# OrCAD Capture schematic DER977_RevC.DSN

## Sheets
1 PAGE3: size A
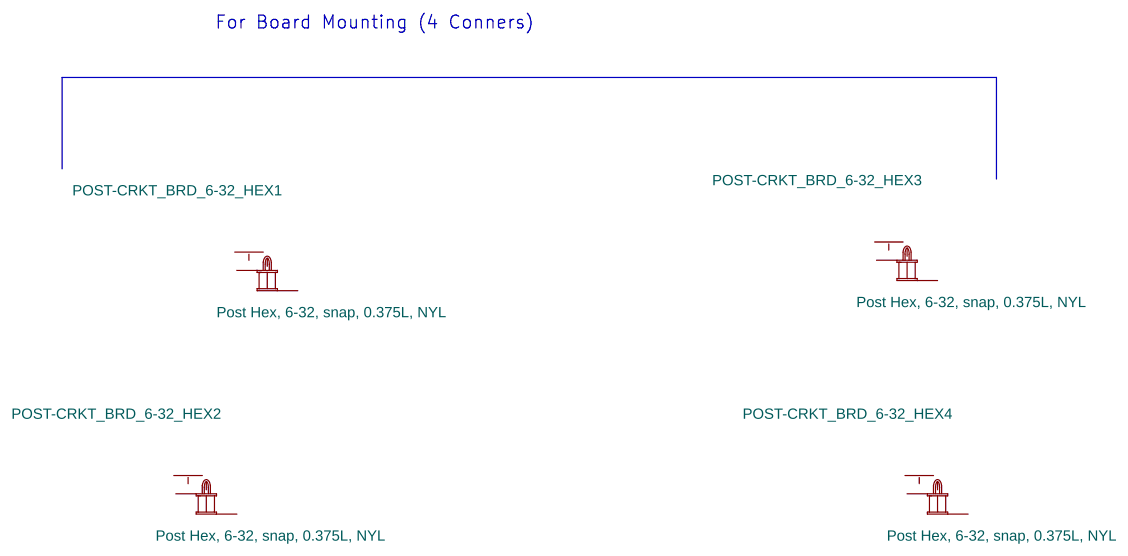
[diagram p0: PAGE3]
2 PAGE2: size C; title: HiperPFS-220W Design
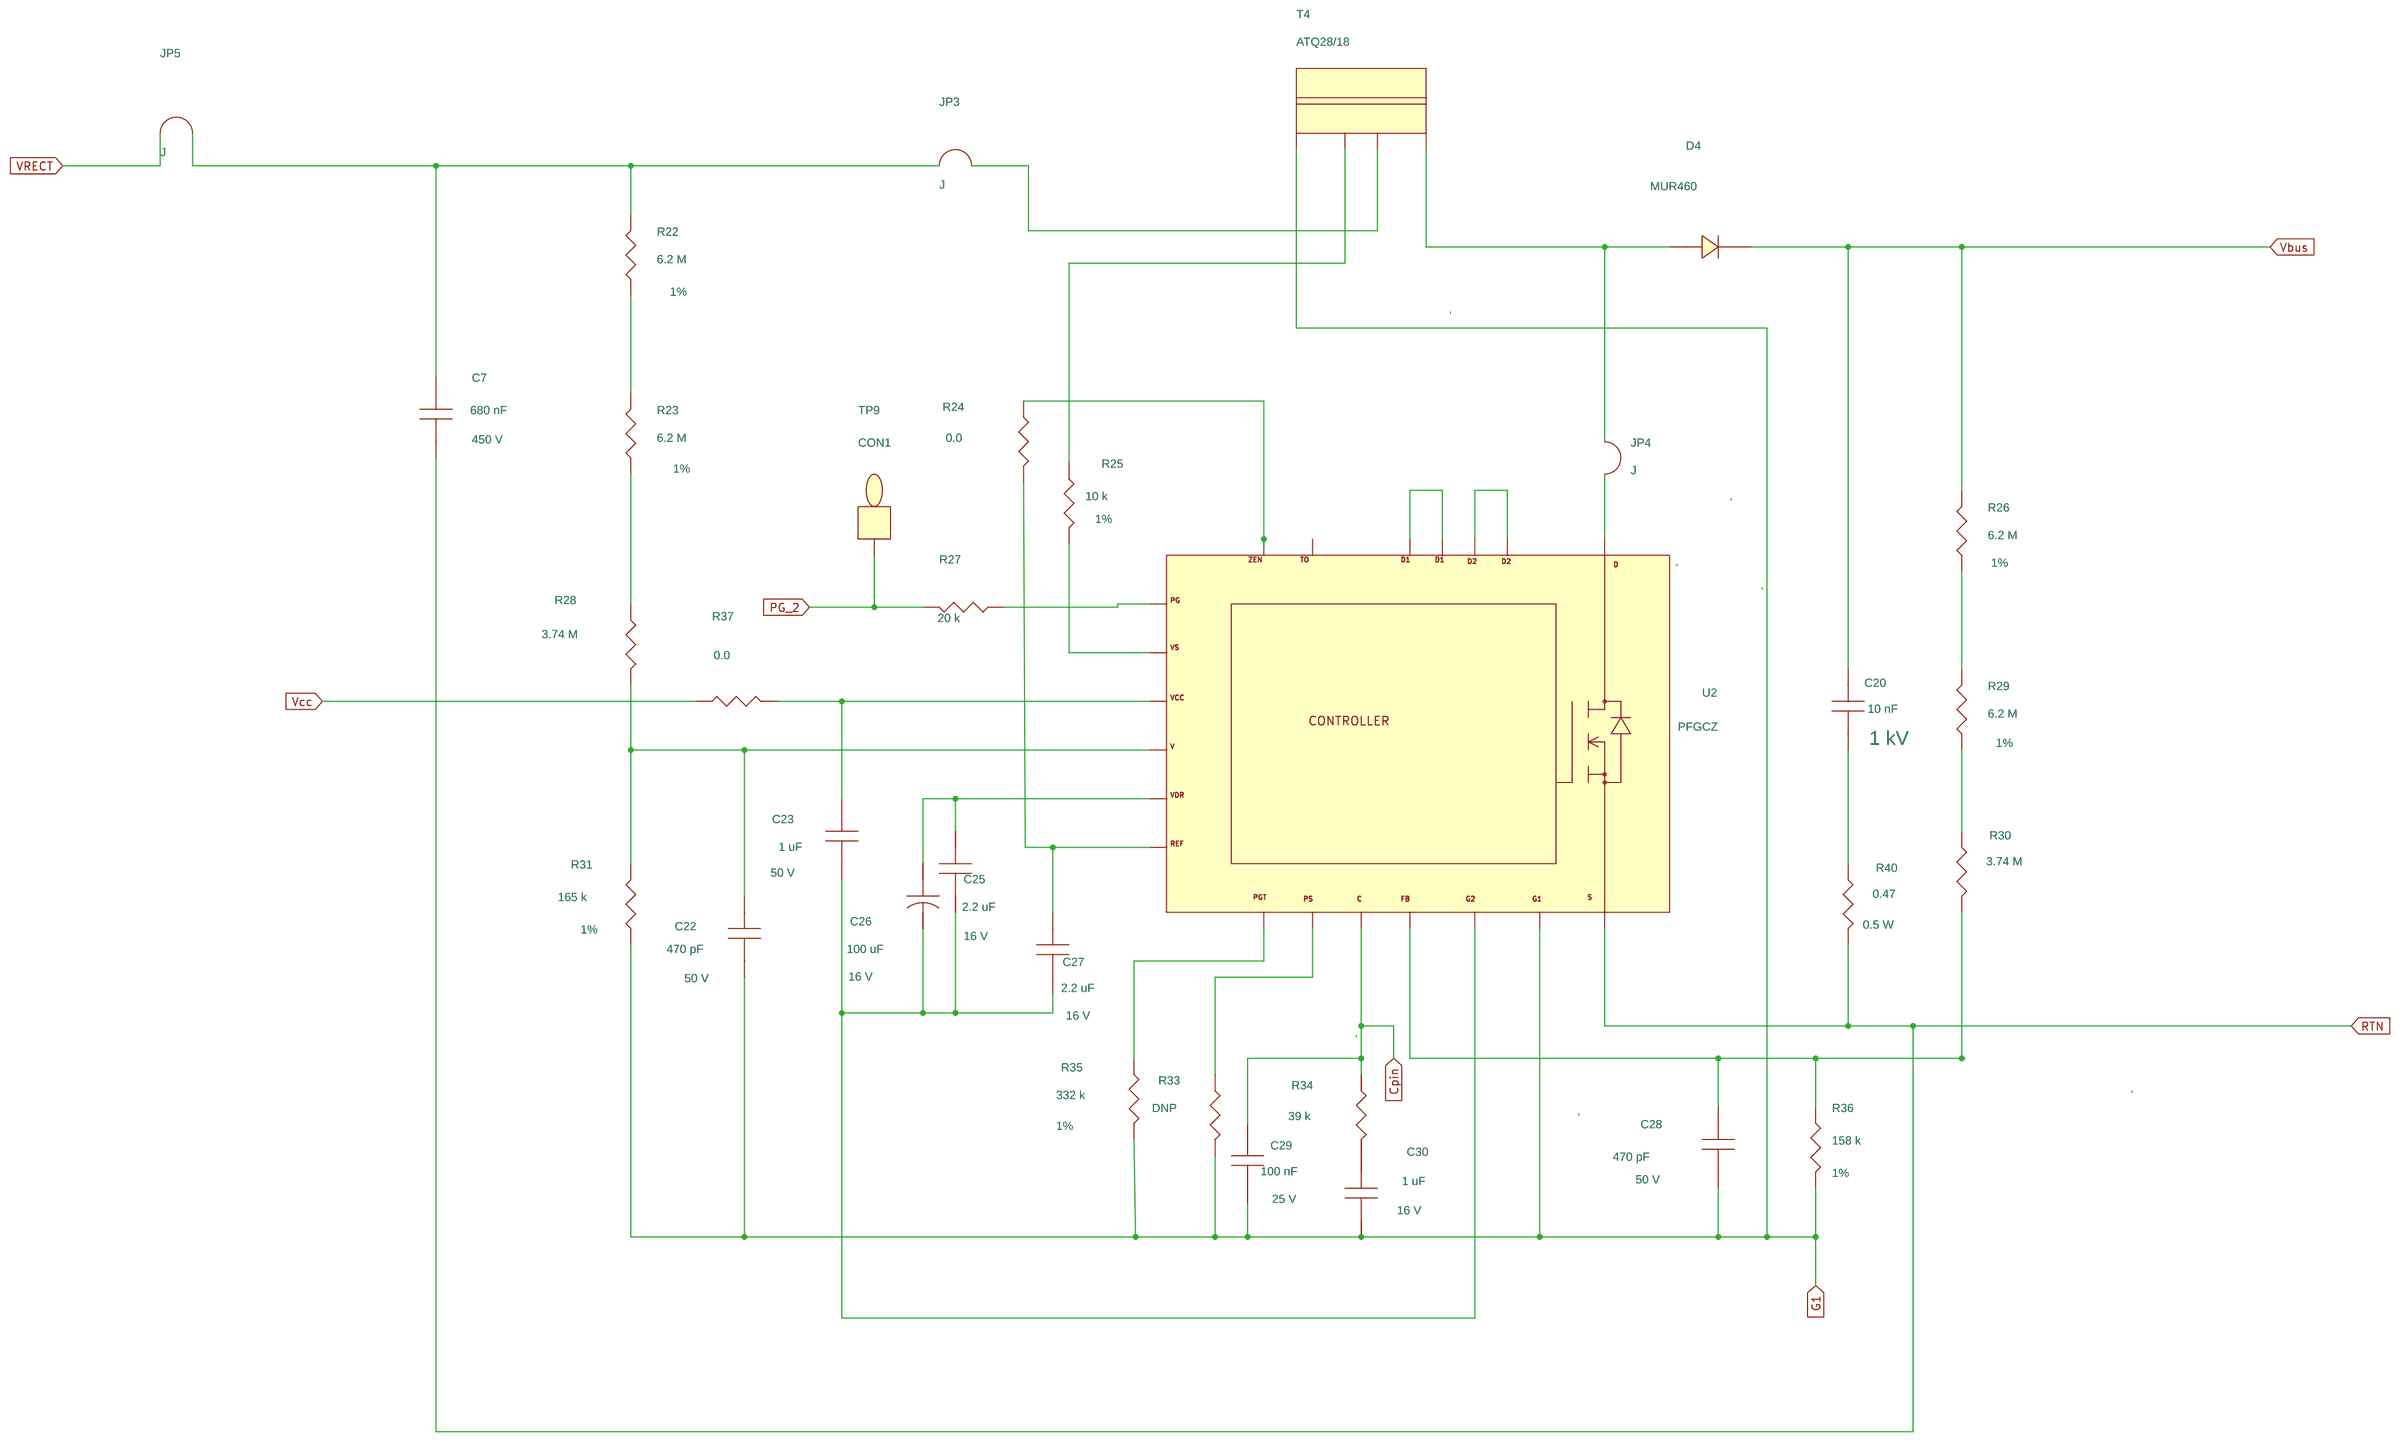
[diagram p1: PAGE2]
3 PAGE1: size C; title: HIPERPFS5 -440W Parallel Board
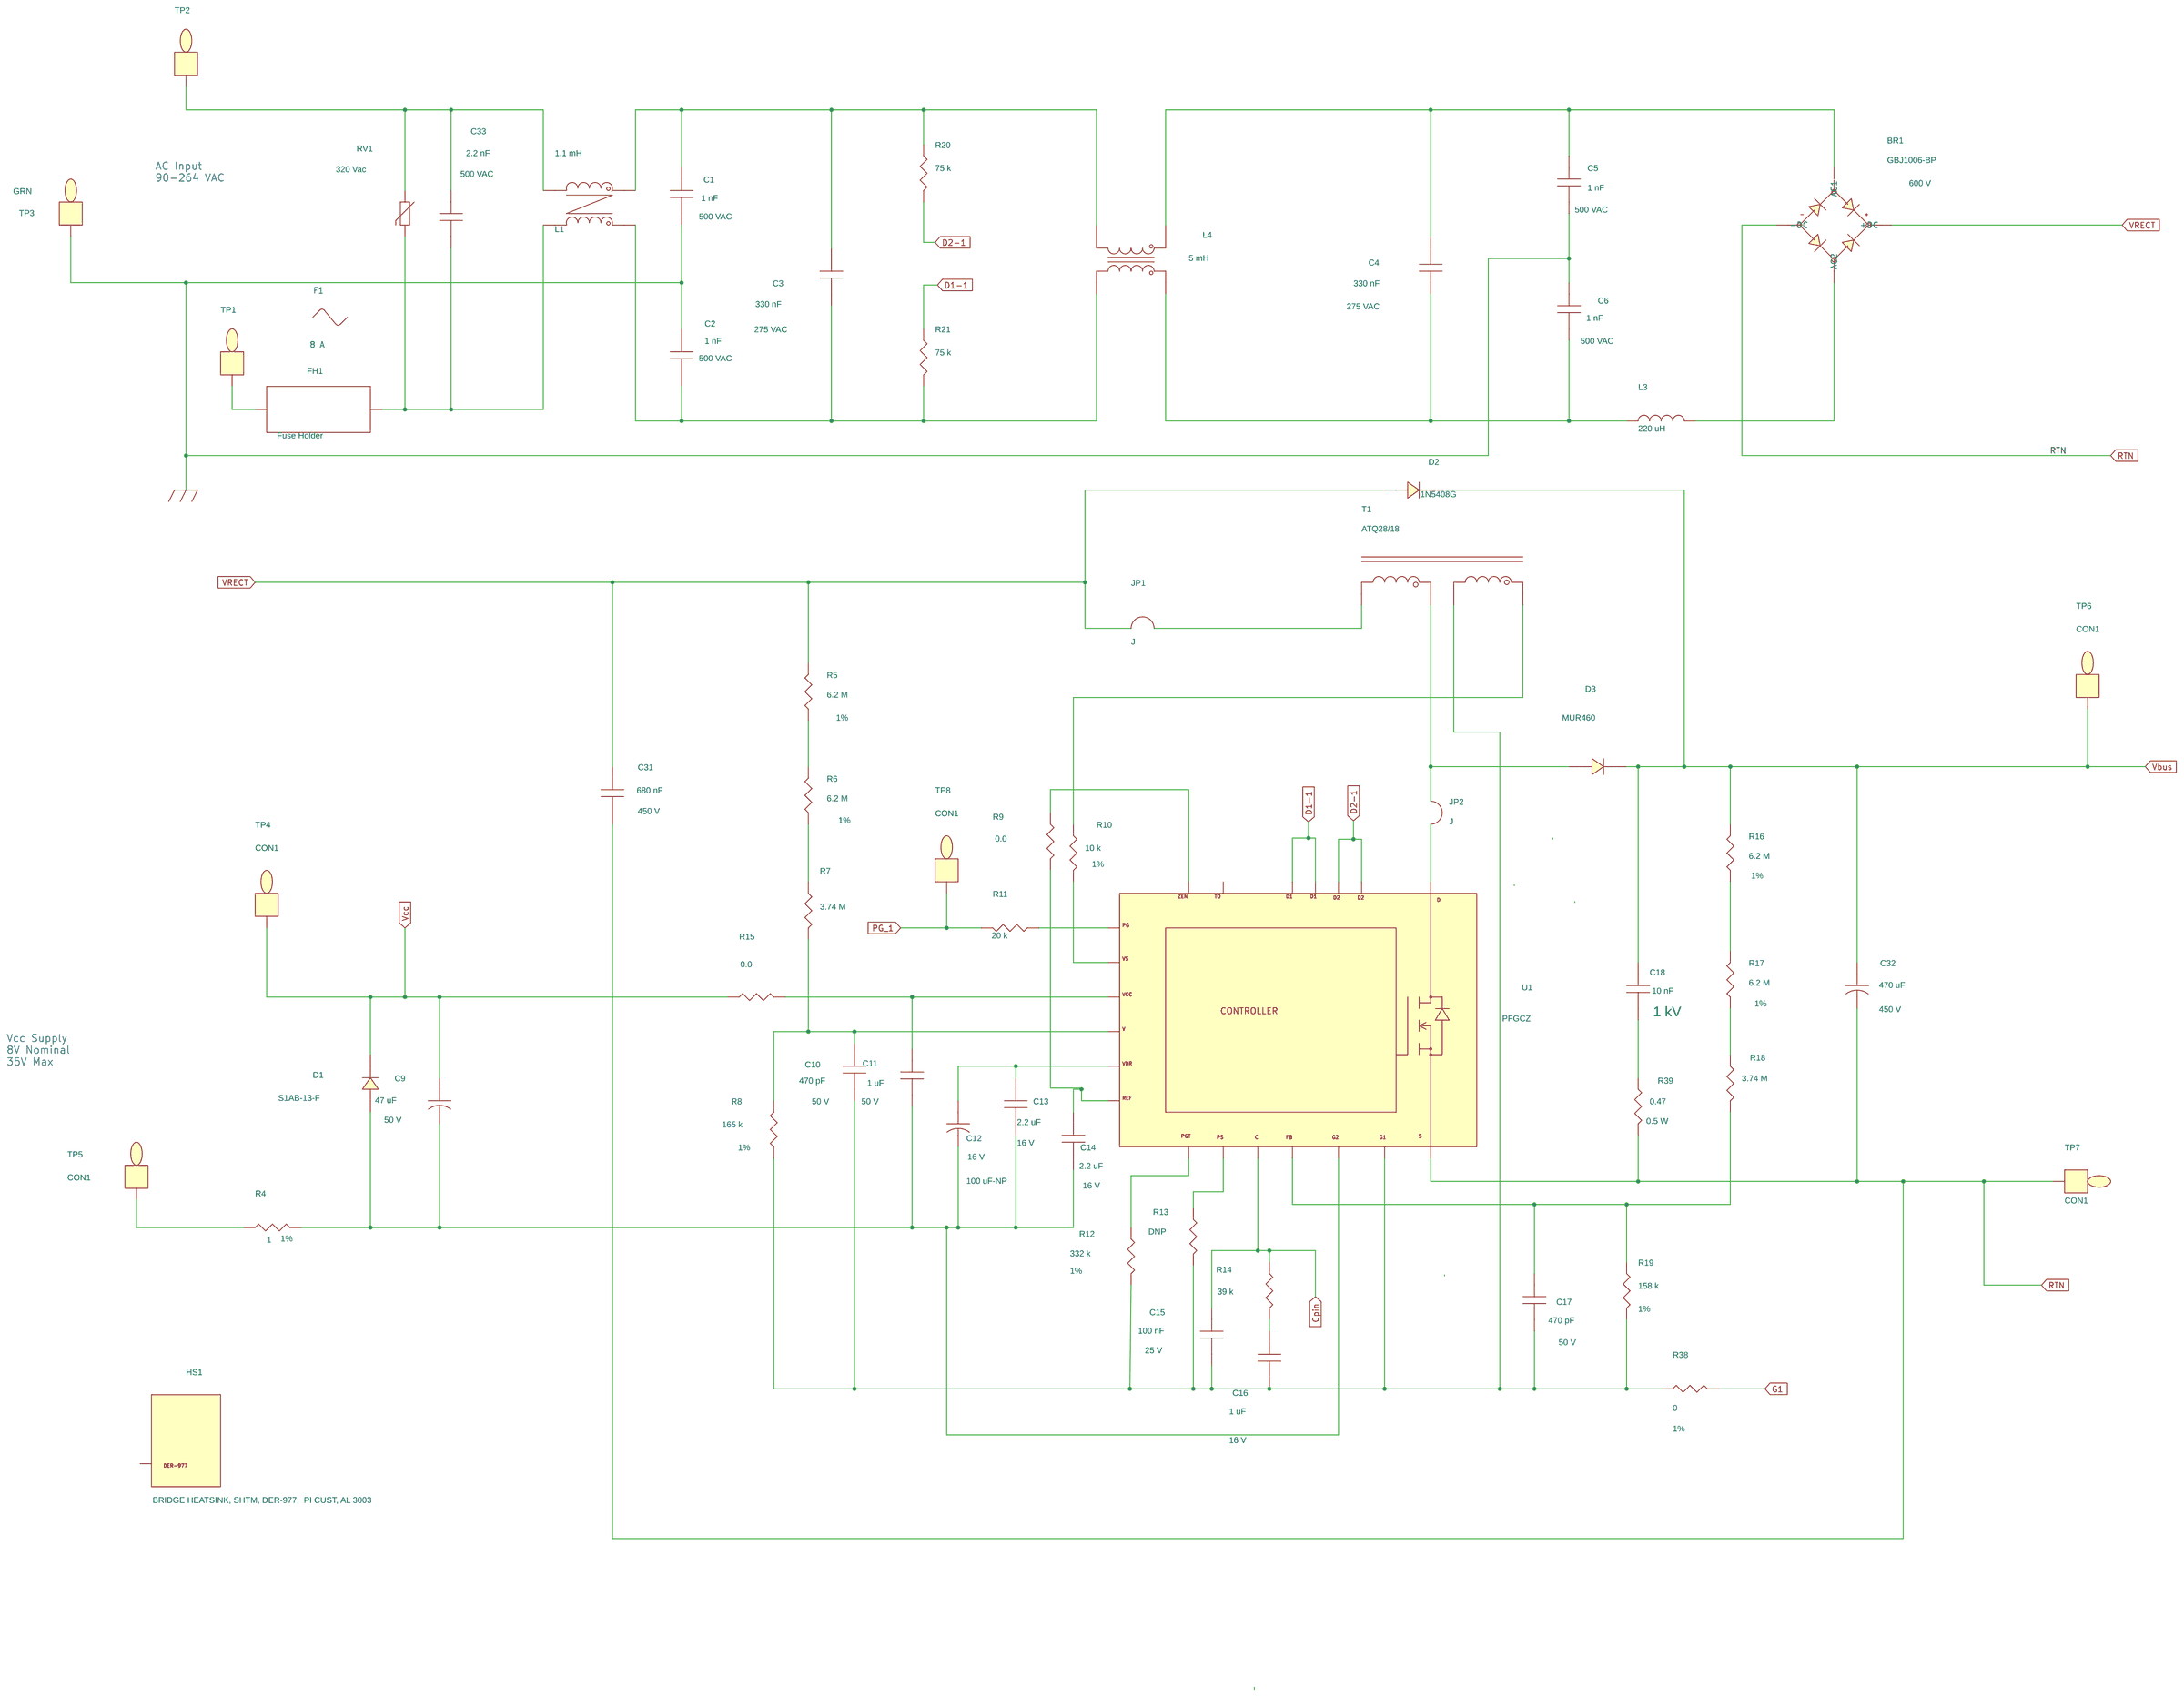
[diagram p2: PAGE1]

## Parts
sheet PAGE1
BR1  GBJ1006-BP  [pi_dax_bridg_gbj]
C1  1 nF  [pi_np475x200ls395d040]
C2  1 nF  [pi_np475x200ls395d040]
C3  330 nF  [pinp_xcaprad15x8p5x14Hd040]
C4  330 nF  [pinp_xcaprad15x8p5x14Hd040]
C5  1 nF  [pi_np475x200ls395d040]
C6  1 nF  [pi_np475x200ls395d040]
C9  47 uF  [pipolcapcyld250ls100030]
C10  470 pF  [pismc0603]
C11  1 uF  [pismc0603]
C12  100 uF-NP  [pipolcapcyld250ls100030]
C13  2.2 uF  [pismc0402]
C14  2.2 uF  [pismc0402]
C15  100 nF  [pismc0603]
C16  1 uF  [pismc0603]
C17  470 pF  [pismc0603]
C18  10 nF  [pi_np_cap250x200ls170d030]
C31  680 nF  [pinpcaprad17p5x6p7ls15]
C32  470 uF  [pipolcapclyd35mmls10]
C33  2.2 nF  [pinpycaprad540x290ls400040]
D1  S1AB-13-F  [pismsmb]
D2  1N5408G  [pidv300x200x060do15d0201ad]
D3  MUR460  [pidv300x200x060do15d0201ad]
F1  8 A
FH1  Fuse Holder  [pi_fuseholder_5x20mm]
HS1  BRIDGE HEATSINK, SHTM, DER-977,  PI CUST, AL 3003  [PI_HS_1P_DER977]
JP1  J  [pi_jumper200]
JP2  J  [pi_jumper200]
L1  1.1 mH  [piind4p22x10ls10mm050]
L3  220 uH  [pi2p30x15x15lsd60]
L4  5 mH  [piind4p1450x800ls900x600050]
R4  1  [pismr1206]
R5  6.2 M  [pismr1206]
R6  6.2 M  [pismr1206]
R7  3.74 M  [pismr1206]
R8  165 k  [pismr0805]
R9  0.0  [pismr0603]
R10  10 k  [pismr0805]
R11  20 k  [pismr0603]
R12  332 k  [pismr0603]
R13  DNP  [pismr0805]
R14  39 k  [pismr0603]
R15  0.0  [pismr0603]
R16  6.2 M  [pismr1206]
R17  6.2 M  [pismr1206]
R18  3.74 M  [pismr1206]
R19  158 k  [pismr0805]
R20  75 k  [pismr1206]
R21  75 k  [pismr1206]
R38  0  [pismr0603]
R39  0.47  [pismr2010]
RV1  320 Vac  [pidisc500x225ls335x140040]
T1  ATQ28/18  [pi_bobbin_ATQ28_V_4P]
TP1  RED  [pitpkeystone125x125]
TP2  CON1  [pitpkeystone125x125]
TP3  GRN  [pitpkeystone125x125]
TP4  CON1  [pitpkeystone125x125]
TP5  CON1  [pitpkeystone125x125]
TP6  CON1  [pitpkeystone125x125]
TP7  CON1  [pitpkeystone125x125]
TP8  CON1  [pitpkeystone125x125]
U1  PFGCZ  [inSOP-T28F]
sheet PAGE2
C7  680 nF  [pinpcaprad17p5x6p7ls15]
C20  10 nF  [pi_np_cap250x200ls170d030]
C22  470 pF  [pismc0603]
C23  1 uF  [pismc0603]
C25  2.2 uF  [pismc0402]
C26  100 uF  [pipolcapcyld250ls100030]
C27  2.2 uF  [pismc0402]
C28  470 pF  [pismc0603]
C29  100 nF  [pismc0603]
C30  1 uF  [pismc0603]
D4  MUR460  [pidv300x200x060do15d0201ad]
JP3  J  [pi_jumper200]
JP4  J  [pi_jumper200]
JP5  J  [pi_jumper1800-18awg-sld]
R22  6.2 M  [pismr1206]
R23  6.2 M  [pismr1206]
R24  0.0  [pismr0603]
R25  10 k  [pismr0805]
R26  6.2 M  [pismr1206]
R27  20 k  [pismr0603]
R28  3.74 M  [pismr1206]
R29  6.2 M  [pismr1206]
R30  3.74 M  [pismr1206]
R31  165 k  [pismr0805]
R33  DNP  [pismr0805]
R34  39 k  [pismr0603]
R35  332 k  [pismr0603]
R36  158 k  [pismr0805]
R37  0.0  [pismr0603]
R40  0.47  [pismr2010]
T4  ATQ28/18  [pi_bobbin_ATQ28_V_4P]
TP9  CON1  [pitpkeystone125x125]
U2  PFGCZ  [inSOP-T28F]
sheet PAGE3
POST-CRKT_BRD_6-32_HEX1  Post Hex, 6-32, snap, 0.375L, NYL  [pimtgholed156]
POST-CRKT_BRD_6-32_HEX2  Post Hex, 6-32, snap, 0.375L, NYL  [pimtgholed156]
POST-CRKT_BRD_6-32_HEX3  Post Hex, 6-32, snap, 0.375L, NYL  [pimtgholed156]
POST-CRKT_BRD_6-32_HEX4  Post Hex, 6-32, snap, 0.375L, NYL  [pimtgholed156]

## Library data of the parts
BR1 = DIODE_BRIDGE_1234: Disp_Voltage: 600 V; Part Number: 15-00791-00
C1 C2 C5 C6 = CAP_NP: Disp_Voltage: 500 VAC; PCB Editor PCBFP: pinpycaprad470x210ls380040; Part Number: 20-01061-00; ROOM: 1; Tol: 20; Voltage: 500 VAC
C3 C4 = CAP_NP: ALT_SYMBOLS: pinp_xcaprad15x8p5x14Hd040H; Disp_Voltage: 275 VAC; FPLIST: pinp_xcaprad15x8p5x14Hd040,pinp_xcaprad15x8p5x14Hd040H; Part Number: 20-09095-00; ROOM: 1; Voltage: 275 VAC
C9 = CAP_POL: ALT_SYMBOLS: pipolcapcyld250ls100030h; Disp_Voltage: 50 V; Part Number: 20-00444-00; ROOM: 2; Tol: 20; Voltage: 50 V
C10 C17 C22 C28 = CAP_NP: Disp_Voltage: 50 V; Part Number: 20-09118-00; ROOM: 2; Voltage: 50 V
C11 C23 = CAP_NP: Disp_Voltage: 50 V; Part Number: 20-09159-00; ROOM: 2; Voltage: 50 V
C12 C26 = CAP_POL: ALT_SYMBOLS: pipolcapcyld250ls100030h; Disp_Voltage: 16 V; FPLIST: pipolcapcyld250ls100030,pipolcapcyld250ls100030h; Part Number: 20-00079-00; ROOM: 2; Tol: 20; Voltage: 16 V
C13 C14 C25 C27 = CAP_NP: ALT_SYMBOLS: pismr0402_1; Disp_Voltage: 16 V; FPLIST: pismc0402,pismr0402_1; Part Number: 20-09202-00; ROOM: 2; Voltage: 16 V
C15 C29 = CAP_NP: Disp_Voltage: 25 V; Part Number: 20-00528-00; ROOM: 2; Voltage: 25 V
C16 C30 = CAP_NP: Disp_Voltage: 16 V; Part Number: 20-01020-00; ROOM: 2; Voltage: 16 V
C18 C20 = CAP_NP: Disp_Voltage: 1 kV; Part Number: 20-00894-00; ROOM: 2; Voltage: 1 kV
C7 C31 = CAP_NP: Disp_Voltage: 450 V; Part Number: 20-01404-00; ROOM: 1; Voltage: 450 V
C32 = CAP_POL: ALT_SYMBOLS: pipolcapclyd35mmls10H; Disp_Voltage: 450 V; FPLIST: pipolcapclyd35mmls10,pipolcapclyd35mmls10H; Part Number: 20-01877-00; Voltage: 450 V
C33 = CAP_NP: ALT_SYMBOLS: pinpycaprad540x290ls400040h; Disp_Voltage: 500 VAC; FPLIST: pinpycaprad540x290ls400040,pinpycaprad540x290ls400040h; Part Number: 20-00376-00; Voltage: 500 VAC
D1 = DIODE: Part Number: 15-00994-00; ROOM: 2
D2 = DIODE: ALT_SYMBOLS: pidv300x472x060do14wbead,pidax800x225060do15do201ad,pidv300x200x060do14wbead; FPLIST: pidv300x200x060do15d0201ad,pidv300x472x060do14wbead,pidax800x225060do15do201ad,pidv300x200x060do14wbead; Part Number: 15-01651-00; ROOM: 2
D3 D4 = DIODE: ALT_SYMBOLS: pidax800x225060do15do201ad,pidv300x200x060do14wbead; FPLIST: pidv300x200x060do15d0201ad,pidax800x225060do15do201ad,pidv300x200x060do14wbead; Part Number: 15-00510-00; ROOM: 2
F1 = FUSE_NoPin: Part Number: 40-00024-00
FH1 = FUSEHOLDER: Part Number: 35-00072-00
HS1 = hs_1P_DER977: FPLIST: PI_HS_1P_DER977,PI_HS_2P_DER977; Part Number: 61-00321-00
JP1-JP4 = JUMPER_1: Part Number: 65-00001-00; ROOM: 2
L1 = CMC__4P_12_43: Part Number: 30-00550-00
L3 = INDUCTOR: Part Number: 30-00548-00; ROOM: 1
L4 = INDUCTOR_4P_revD: Part Number: 30-00403-00
R4 = R: Disp_Tol: 1%; Part Number: 05-00481-00; ROOM: 2
R5 R6 R16 R17 R22 R23 R26 R29 = R: Disp_Tol: 1%; Part Number: 05-05567-00; ROOM: 2
R7 R18 R28 R30 = R: Part Number: 05-05572-00; ROOM: 2
R8 R31 = R: Disp_Tol: 1%; Part Number: 05-00801-00; ROOM: 2
R9 R24 = R: Part Number: 05-03158-00; ROOM: 2
R10 R25 = R: Disp_Tol: 1%; Part Number: 05-00684-00; ROOM: 2
R11 R27 = R: Part Number: 05-01719-00; ROOM: 2
R12 R35 = R: Disp_Tol: 1%; Part Number: 05-01224-00; ROOM: 2
R13 R33 = R: Part Number: 05-01573-00; ROOM: 2
R14 R34 = R: Part Number: 05-01726-00; ROOM: 2
R15 R37 = R: Part Number: 05-03158-00
R19 R36 = R: Disp_Tol: 1%; Part Number: 05-00799-00; ROOM: 2
R20 R21 = R: Part Number: 05-01397-00; ROOM: 1
R38 = R: Disp_Tol: 1%; Part Number: 05-06654-00
R39 R40 = R: Disp_Power: 0.5 W; Part Number: 05-03165-00; ROOM: 2
RV1 = VARISTOR: Part Number: 85-00018-00; ROOM: 1
T1 = Transformer_DER-977_PFSGAN_250W: Part Number: 25-01199-00
TP1 = TESTPOINT: Part Number: 35-00043-00; ROOM: 1
TP2 = TESTPOINT: Part Number: 35-00044-00; ROOM: 1
TP3 = TESTPOINT: Part Number: 35-00187-00
TP4 TP6-TP9 = TESTPOINT: Part Number: 35-00043-00; ROOM: 2
TP5 = TESTPOINT: Part Number: 35-00042-00; ROOM: 2
U1 U2 = PFSGaN_InSOP-T28F28: Part Number: 10-01271-00; ROOM: 2
JP5 = JUMPER_1: Part Number: 65-00096-00
T4 = BATQ28_4P_GENERIC: ALT_SYMBOLS: pi_bobbin_ATQ28_V_5P; FPLIST: pi_bobbin_ATQ28_V_4P,pi_bobbin_ATQ28_V_5P; Part Number: 25-01170-00
POST-CRKT_BRD_6-32_HEX1-POST-CRKT_BRD_6-32_HEX4 = POST_CRKT_BRD_6-32_HEX: Part Number: 76-00003-00

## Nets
GND_EARTH: C1.2 C2.1 C5.2 C6.1 TP3.1
Vbus: C18.1 C20.1 C32.1 D2.1 D3.1 D4.1 R16.2 R26.2 TP6.1
Vcc: C9.1 D1.1 R15.1 R37.1 TP4.1
Cpin: C15.1 C29.1 R14.1 R34.1 U1.5 U2.5
D1-1: R21.1 U1.15 U1.16
D2-1: R20.2 U1.18 U1.19
G1: C22.2 C28.2 C29.2 C30.2 R31.2 R33.2 R35.2 R36.2 R38.2 T4.1 U2.2
PG_1: R11.1 TP8.1
PG_2: R27.1 TP9.1
RTN: BR1.4(-DC) C7.2 C31.2 C32.2 R39.2 R40.2 TP7.1 U1.21 U2.21
VRECT: BR1.1(+DC) C31.1 D2.2 JP1.1 JP5.1 R5.2
N2269146: FH1.1 TP1.1
N2269222: C1.1 C3.1 L1.4 L4.3 R20.1
N2269270: BR1.2(AC1) C4.2 C5.1 L4.4
N2269580: C4.1 C6.2 L3.1 L4.1
N2273543: C10.1 R7.2 R8.1 U1.4
N2273803: R4.1 TP5.1
N2273811: C9.2 C11.2 C12.2 C13.2 C14.2 D1.2 R4.2 U1.13
N2277982: R5.1 R6.2
N2280643: C10.2 C15.2 C16.2 C17.2 R8.2 R12.2 R13.2 R19.2 R38.1 T1.1 U1.2
N2280913: R13.1 U1.9
N2282320: C12.1 C13.1 U1.12
N2282978: C14.1 R9.2 U1.11
N2283364: R12.1 U1.8
N2283809: R10.2 U1.1
N2285705: C11.1 R15.2 U1.14
N2292996: C17.1 R18.2 R19.1 U1.6
N12253154: R16.1 R17.2
N12253176: R17.1 R18.1
N12296335: R11.2 U1.7
N12310541: R9.1 U1.10
N12311649: C33.1 L1.3 RV1.1 TP2.1
N12311801: C33.2 FH1.2 L1.2 RV1.2
N12332974: JP1.2 T1.3
N12355245: JP2.2 U1.28
N12357298: BR1.3(AC2) L3.2
N12358168: C2.2 C3.2 L1.1 L4.2 R21.2
N12370171: C7.1 JP3.1 JP5.2 R22.2
N12370179: JP3.2 T4.3
N12370191: R25.1 T4.2
N12370241: R22.1 R23.2
N12370315: R24.1 U2.10
N12370431: C27.1 R24.2 U2.11
N12370475: U2.15 U2.16
N12370487: U2.18 U2.19
N12370503: JP4.2 U2.28
N12370525: R25.2 U2.1
N12370581: R26.1 R29.2
N12370631: R27.2 U2.7
N12370663: C22.1 R28.2 R31.1 U2.4
N12370753: C23.1 R37.2 U2.14
N12370795: R29.1 R30.1
N12370825: C25.1 C26.1 U2.12
N12370935: C23.2 C25.2 C26.2 C27.2 U2.13
N12371013: R35.1 U2.8
N12371017: R33.1 U2.9
N12371025: C28.1 R30.2 R36.1 U2.6
N12389668: R6.1 R7.1
N12393657: R10.1 T1.2
N12394061: D3.2 JP2.1 T1.4
N12395901: R23.1 R28.1
N12410952: D4.2 JP4.1 T4.4
N12423276: C16.1 R14.2
N12448428: C18.2 R39.1
N12448931: C20.2 R40.1
N12449141: C30.1 R34.2

Not connected (* = marked no-connect by the designer): HS1 1; POST-CRKT_BRD_6-32_HEX1 1; POST-CRKT_BRD_6-32_HEX2 1; POST-CRKT_BRD_6-32_HEX3 1; POST-CRKT_BRD_6-32_HEX4 1; U1 3; U2 3

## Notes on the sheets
sheet 1
- For Board Mounting (4 Conners)
sheet 3
- AC Input
  90-264 VAC
- Vcc Supply
  8V Nominal
  35V Max
